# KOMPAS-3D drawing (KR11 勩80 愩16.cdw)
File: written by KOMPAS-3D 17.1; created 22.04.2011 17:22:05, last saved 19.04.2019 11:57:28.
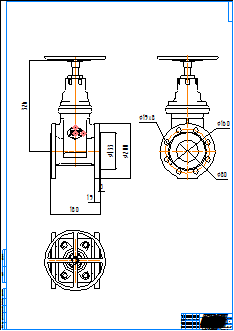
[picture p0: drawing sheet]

Title block, sheet 1: name: KR11 Ду80 Ру16; material: Внимание! Данный продукт является объектом авторского права ООО «Торговый Дом АДЛ». / Запрещается изменение, копирование, распространение / (в том числе путем копирования на другие сайты и ресурсы в Интернете) / или любое иное использование информации и объектов без предварительного / согласия правообладателя (ООО «Торговый Дом АДЛ»).; scale: 1:1; sheets: 1; organisation: ООО "Торговый дом АДЛ"; sheet format: A0; stored path: \\adlc.lan\data\АДЛ_ПКД\3D-модели\ADL production\Клиновые задвижки серии KR ГРАНАР\Клиновые задвижки KR11\KOMPAS 2D\KR11 Ду80 Ру16.cdw

Views: Спереди 4, Проекционный вид 5, Проекционный вид 6
Dimensions and other numbers on the sheet: 200; 133; 180; 3; 19; 326; 160; 80; 1:1; 1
